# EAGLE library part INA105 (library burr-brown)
Precision Unity Gain Diff. Amplifier
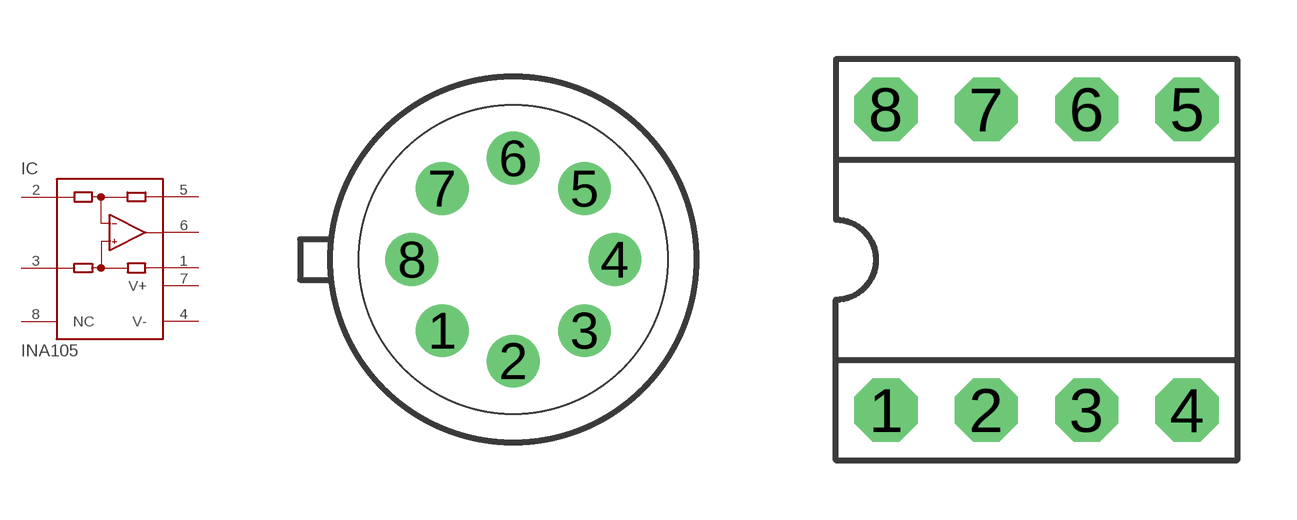
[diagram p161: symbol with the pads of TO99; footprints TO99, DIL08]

Designator prefix IC

## INA105M (MF: TEXAS INSTRUMENT CONNECTORS; MPN: INA105BM; OC_FARNELL: 1459423; OC_NEWARK: 88K1114)  [TO99]
1  REF  pas
2  -IN  in
3  +IN  in
4  V-  pwr
5  SENSE  pas
6  OUT  out
7  V+  pwr
8  NC  nc

## INA105P (MF: TEXAS INSTRUMENTS; MPN: INA105KP; OC_FARNELL: 1651850; OC_NEWARK: 04M4538)  [DIL08]
Pads as for TO99

## INA105U (MF: TEXAS INSTRUMENTS; MPN: INA105KU; OC_FARNELL: 1754832; OC_NEWARK: 35C0475)  [SO08]
Pads as for TO99

## Footprint TO99 (pad centres in mm)
Metal can Package
drill 0.813 round: 1 -1.778,-1.778; 2 0,-2.54; 3 1.778,-1.778; 4 2.54,0; 5 1.778,1.778; 6 0,2.54; 7 -1.778,1.778; 8 -2.54,0

## Footprint DIL08 (pad centres in mm)
Dual In Line
drill 0.813 pad 1.6 octagon: 1 -3.81,-3.81; 2 -1.27,-3.81; 3 1.27,-3.81; 4 3.81,-3.81; 5 3.81,3.81; 6 1.27,3.81; 7 -1.27,3.81; 8 -3.81,3.81

## Footprint SO08 (pad centres in mm)
Small Outline Package
smd 0.61 x 2.21: 1 -1.905,-2.616; 2 -0.635,-2.616; 3 0.635,-2.616; 4 1.905,-2.616; 5 1.905,2.616; 6 0.635,2.616; 7 -0.635,2.616; 8 -1.905,2.616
